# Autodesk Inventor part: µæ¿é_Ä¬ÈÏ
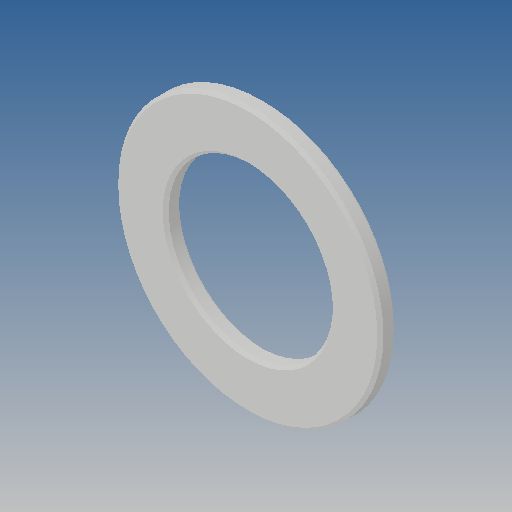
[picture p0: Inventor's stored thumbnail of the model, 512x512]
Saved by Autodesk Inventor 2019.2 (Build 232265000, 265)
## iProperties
Created: 2011-12
Part Number: µæ¿é_Ä¬ÈÏ
Material: Ogólny
Document SubType Name: Modeling
Designer: CADENGINEERING4
Density: 1 g/cm^3
Appearance: Domyślna
Author: CADENGINEERING4
Revision Number: ÈÎºÎ
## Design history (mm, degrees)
feature "NONE"
node "Bryła1"
